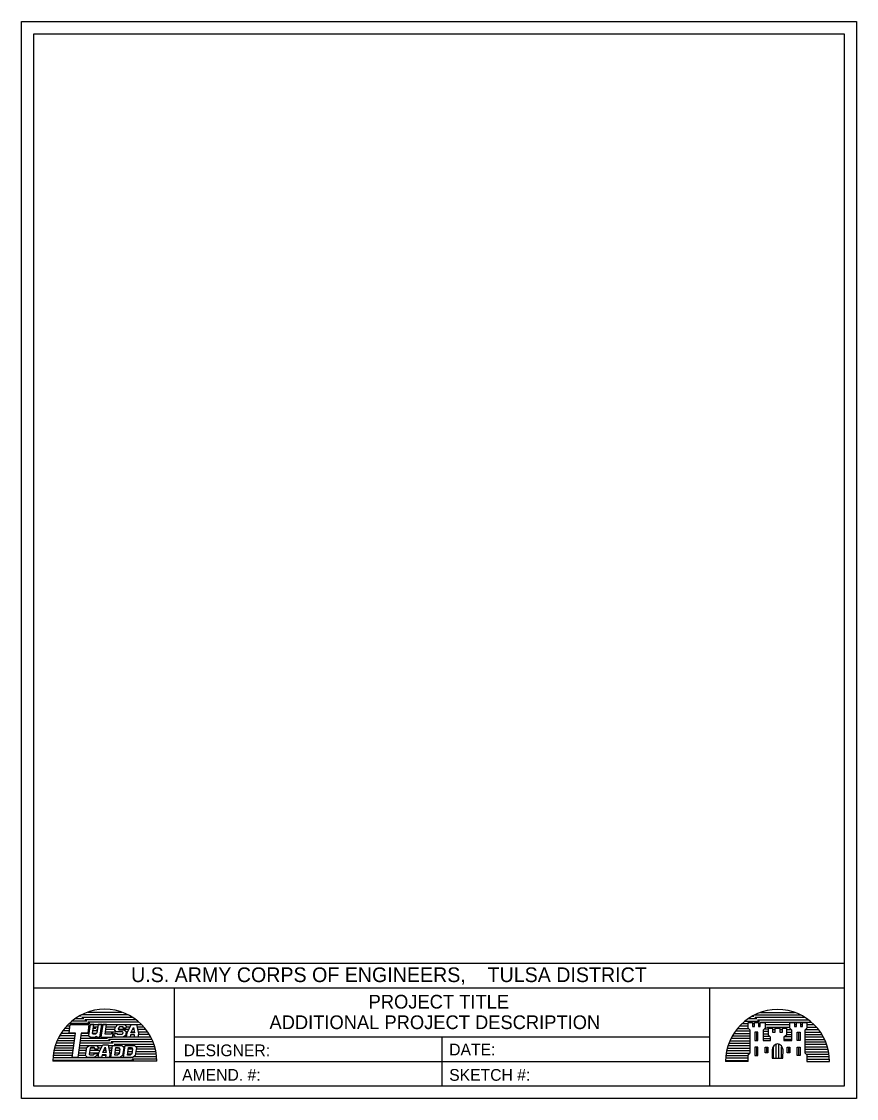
# Model space of a CAD drawing. Extents: x -12225.15 to -12224.44, y -12111.632 to -12110.717.
import ezdxf

# ---------------------------------------------------------------- set-up
doc = ezdxf.new("R2010")
doc.units = 0
for name, color, linetype in [('G-ANNO-SYMB', 7, 'Continuous'), ('G-ANNO-TEXT', 7, 'Continuous'), ('G-ANNO-TTLB', 7, 'Continuous')]:
    doc.layers.add(name, color=color, linetype=linetype)

msp = doc.modelspace()

# ---------------------------------------------------------------- linework, layer by layer
at = {"layer": 'G-ANNO-SYMB'}
for p, q in [((-12225.09726, -12111.56405), (-12225.10484, -12111.56405)), ((-12225.09975, -12111.56196), (-12225.10156, -12111.56196)), ((-12225.09896, -12111.56056), (-12225.06005, -12111.56056)), ((-12225.09893, -12111.56267), (-12225.05626, -12111.56267)), ((-12225.09394, -12111.55848), (-12225.06506, -12111.55848)), ((-12224.52524, -12111.56426), (-12224.53283, -12111.56426)), ((-12224.52773, -12111.56218), (-12224.52954, -12111.56218)), ((-12224.52694, -12111.56078), (-12224.48803, -12111.56078)), ((-12224.52691, -12111.56288), (-12224.48425, -12111.56288)), ((-12224.52191, -12111.5587), (-12224.49304, -12111.5587)), ((-12225.10934, -12111.57241), (-12225.11381, -12111.57241)), ((-12225.10907, -12111.5703), (-12225.11201, -12111.5703)), ((-12225.09228, -12111.56823), (-12225.10996, -12111.56823)), ((-12225.09477, -12111.56614), (-12225.10759, -12111.56614)), ((-12225.09644, -12111.56474), (-12225.0532, -12111.56474)), ((-12225.09394, -12111.56683), (-12225.05059, -12111.56683)), ((-12225.09246, -12111.57241), (-12225.0935, -12111.57241)), ((-12225.09211, -12111.5703), (-12225.09324, -12111.5703)), ((-12225.09145, -12111.56892), (-12225.04833, -12111.56892)), ((-12225.0873, -12111.57241), (-12225.08945, -12111.57241)), ((-12225.08896, -12111.57102), (-12225.0854, -12111.57102)), ((-12225.08648, -12111.57309), (-12225.08571, -12111.57309)), ((-12225.08267, -12111.57309), (-12225.08178, -12111.57309)), ((-12225.08242, -12111.57102), (-12225.08146, -12111.57102)), ((-12225.07869, -12111.57309), (-12225.07086, -12111.57309)), ((-12225.07836, -12111.57102), (-12225.07023, -12111.57102)), ((-12225.06815, -12111.57309), (-12225.05899, -12111.57309)), ((-12225.06133, -12111.57102), (-12225.05804, -12111.57102)), ((-12225.05596, -12111.57309), (-12225.05475, -12111.57309)), ((-12225.05199, -12111.57102), (-12225.04636, -12111.57102)), ((-12225.05161, -12111.57309), (-12225.04464, -12111.57309)), ((-12224.53218, -12111.57261), (-12224.54179, -12111.57261)), ((-12224.5326, -12111.57053), (-12224.53999, -12111.57053)), ((-12224.5326, -12111.56845), (-12224.53794, -12111.56845)), ((-12224.52275, -12111.56635), (-12224.53558, -12111.56635)), ((-12224.52717, -12111.56845), (-12224.52889, -12111.56845)), ((-12224.52442, -12111.56497), (-12224.48117, -12111.56497)), ((-12224.5222, -12111.56845), (-12224.52378, -12111.56845)), ((-12224.52192, -12111.56705), (-12224.47856, -12111.56705)), ((-12224.51843, -12111.57261), (-12224.51528, -12111.57261)), ((-12224.518, -12111.56914), (-12224.49711, -12111.56914)), ((-12224.51694, -12111.57123), (-12224.49706, -12111.57123)), ((-12224.51178, -12111.57331), (-12224.50963, -12111.57331)), ((-12224.50545, -12111.57331), (-12224.50343, -12111.57331)), ((-12224.50001, -12111.57331), (-12224.49606, -12111.57331)), ((-12224.49293, -12111.56914), (-12224.49132, -12111.56914)), ((-12224.48788, -12111.56914), (-12224.48634, -12111.56914)), ((-12224.4835, -12111.57331), (-12224.47261, -12111.57331)), ((-12224.48254, -12111.57123), (-12224.47434, -12111.57123)), ((-12224.48249, -12111.56914), (-12224.4763, -12111.56914)), ((-12225.105, -12111.58076), (-12225.11917, -12111.58076)), ((-12225.10457, -12111.57866), (-12225.11807, -12111.57866)), ((-12225.10435, -12111.57658), (-12225.11682, -12111.57658)), ((-12225.10959, -12111.57449), (-12225.11542, -12111.57449)), ((-12225.07734, -12111.58076), (-12225.10013, -12111.58076)), ((-12225.09289, -12111.57866), (-12225.09983, -12111.57866)), ((-12225.09303, -12111.57658), (-12225.09954, -12111.57658)), ((-12225.09273, -12111.57449), (-12225.09376, -12111.57449)), ((-12225.08682, -12111.57658), (-12225.09007, -12111.57658)), ((-12225.08593, -12111.57449), (-12225.08976, -12111.57449)), ((-12225.0826, -12111.57866), (-12225.08357, -12111.57866)), ((-12225.08232, -12111.57658), (-12225.08327, -12111.57658)), ((-12225.08306, -12111.57519), (-12225.08209, -12111.57519)), ((-12225.07902, -12111.57519), (-12225.07008, -12111.57519)), ((-12225.07652, -12111.58145), (-12225.03951, -12111.58145)), ((-12225.07292, -12111.57938), (-12225.07058, -12111.57938)), ((-12225.07258, -12111.57727), (-12225.0715, -12111.57727)), ((-12225.06329, -12111.57938), (-12225.06101, -12111.57938)), ((-12225.06181, -12111.57727), (-12225.06072, -12111.57727)), ((-12225.06133, -12111.57519), (-12225.06011, -12111.57519)), ((-12225.05792, -12111.57938), (-12225.05439, -12111.57938)), ((-12225.05692, -12111.57519), (-12225.05439, -12111.57519)), ((-12225.05125, -12111.57519), (-12225.04309, -12111.57519)), ((-12225.05122, -12111.57938), (-12225.04056, -12111.57938)), ((-12225.051, -12111.57727), (-12225.04176, -12111.57727)), ((-12224.53089, -12111.58097), (-12224.54714, -12111.58097)), ((-12224.53089, -12111.57889), (-12224.54605, -12111.57889)), ((-12224.53089, -12111.5768), (-12224.54479, -12111.5768)), ((-12224.53089, -12111.57471), (-12224.54339, -12111.57471)), ((-12224.52548, -12111.57557), (-12224.52548, -12111.58268)), ((-12224.51971, -12111.57471), (-12224.51508, -12111.57471)), ((-12224.51971, -12111.5768), (-12224.51508, -12111.5768)), ((-12224.51971, -12111.57889), (-12224.51425, -12111.57889)), ((-12224.51971, -12111.58097), (-12224.51339, -12111.58097)), ((-12224.51178, -12111.57541), (-12224.50963, -12111.57541)), ((-12224.50545, -12111.57541), (-12224.50343, -12111.57541)), ((-12224.4955, -12111.58167), (-12224.50218, -12111.58167)), ((-12224.4955, -12111.57958), (-12224.50194, -12111.57958)), ((-12224.50002, -12111.57541), (-12224.4955, -12111.57541)), ((-12224.50002, -12111.57749), (-12224.4955, -12111.57749)), ((-12224.48964, -12111.57557), (-12224.48964, -12111.58268)), ((-12224.4842, -12111.57541), (-12224.47108, -12111.57541)), ((-12224.4842, -12111.57749), (-12224.46973, -12111.57749)), ((-12224.4842, -12111.57958), (-12224.46853, -12111.57958)), ((-12224.4842, -12111.58167), (-12224.46748, -12111.58167)), ((-12225.1065, -12111.5912), (-12225.12277, -12111.5912)), ((-12225.10619, -12111.58911), (-12225.12226, -12111.58911)), ((-12225.10586, -12111.58701), (-12225.12167, -12111.58701)), ((-12225.10556, -12111.58494), (-12225.12095, -12111.58494)), ((-12225.10527, -12111.58284), (-12225.12011, -12111.58284)), ((-12225.09523, -12111.5912), (-12225.10159, -12111.5912)), ((-12225.09492, -12111.58911), (-12225.10134, -12111.58911)), ((-12225.093, -12111.58701), (-12225.101, -12111.58701)), ((-12225.07238, -12111.58494), (-12225.10073, -12111.58494)), ((-12225.07486, -12111.58284), (-12225.10043, -12111.58284)), ((-12225.08377, -12111.5912), (-12225.09225, -12111.5912)), ((-12225.08823, -12111.58911), (-12225.09193, -12111.58911)), ((-12225.08167, -12111.58701), (-12225.08649, -12111.58701)), ((-12225.08273, -12111.58911), (-12225.08521, -12111.58911)), ((-12225.07854, -12111.5912), (-12225.08063, -12111.5912)), ((-12225.07895, -12111.58911), (-12225.0796, -12111.58911)), ((-12225.07303, -12111.58701), (-12225.07649, -12111.58701)), ((-12225.07333, -12111.58911), (-12225.07607, -12111.58911)), ((-12225.07366, -12111.5912), (-12225.07567, -12111.5912)), ((-12225.07403, -12111.58354), (-12225.03859, -12111.58354)), ((-12225.07155, -12111.58563), (-12225.0378, -12111.58563)), ((-12225.06696, -12111.5912), (-12225.07053, -12111.5912)), ((-12225.06741, -12111.58911), (-12225.07021, -12111.58911)), ((-12225.0642, -12111.58772), (-12225.06228, -12111.58772)), ((-12225.06399, -12111.5919), (-12225.06295, -12111.5919)), ((-12225.06369, -12111.5898), (-12225.06259, -12111.5898)), ((-12225.05974, -12111.5919), (-12225.05623, -12111.5919)), ((-12225.05947, -12111.5898), (-12225.05593, -12111.5898)), ((-12225.05334, -12111.58772), (-12225.03713, -12111.58772)), ((-12225.05314, -12111.5919), (-12225.03613, -12111.5919)), ((-12225.05285, -12111.5898), (-12225.03656, -12111.5898)), ((-12224.53089, -12111.59141), (-12224.55073, -12111.59141)), ((-12224.53089, -12111.58932), (-12224.55025, -12111.58932)), ((-12224.53089, -12111.58724), (-12224.54964, -12111.58724)), ((-12224.53089, -12111.58516), (-12224.54894, -12111.58516)), ((-12224.53089, -12111.58305), (-12224.5481, -12111.58305)), ((-12224.52548, -12111.58829), (-12224.52548, -12111.59541)), ((-12224.51694, -12111.58813), (-12224.51694, -12111.5931)), ((-12224.51085, -12111.59764), (-12224.51085, -12111.58793)), ((-12224.50861, -12111.59764), (-12224.50861, -12111.58602)), ((-12224.5064, -12111.59764), (-12224.5064, -12111.58601)), ((-12224.50417, -12111.59764), (-12224.50417, -12111.58793)), ((-12224.49817, -12111.58813), (-12224.49817, -12111.5931)), ((-12224.48964, -12111.58829), (-12224.48964, -12111.59541)), ((-12224.4842, -12111.58376), (-12224.46657, -12111.58376)), ((-12224.4842, -12111.58584), (-12224.46578, -12111.58584)), ((-12224.4842, -12111.58794), (-12224.46511, -12111.58794)), ((-12224.4842, -12111.59002), (-12224.46455, -12111.59002)), ((-12225.05496, -12111.59955), (-12225.12371, -12111.59955)), ((-12225.03532, -12111.60025), (-12225.12371, -12111.60025)), ((-12225.05745, -12111.59746), (-12225.1236, -12111.59746)), ((-12225.10706, -12111.59536), (-12225.12342, -12111.59536)), ((-12225.10678, -12111.59329), (-12225.12315, -12111.59329)), ((-12225.09569, -12111.59536), (-12225.10232, -12111.59536)), ((-12225.09555, -12111.59329), (-12225.10195, -12111.59329)), ((-12225.08483, -12111.59329), (-12225.09257, -12111.59329)), ((-12225.08497, -12111.59536), (-12225.08635, -12111.59536)), ((-12225.07827, -12111.59536), (-12225.082, -12111.59536)), ((-12225.0741, -12111.59536), (-12225.07531, -12111.59536)), ((-12225.07397, -12111.59329), (-12225.07525, -12111.59329)), ((-12225.06722, -12111.59329), (-12225.07086, -12111.59329)), ((-12225.06343, -12111.59536), (-12225.06445, -12111.59536)), ((-12225.06011, -12111.59398), (-12225.05652, -12111.59398)), ((-12225.05661, -12111.59815), (-12225.03536, -12111.59815)), ((-12225.05464, -12111.59607), (-12225.03551, -12111.59607)), ((-12225.05344, -12111.59398), (-12225.03575, -12111.59398)), ((-12224.5326, -12111.59976), (-12224.55168, -12111.59976)), ((-12224.5326, -12111.60046), (-12224.55168, -12111.60046)), ((-12224.5326, -12111.59768), (-12224.55158, -12111.59768)), ((-12224.5326, -12111.59559), (-12224.5514, -12111.59559)), ((-12224.53123, -12111.59351), (-12224.55113, -12111.59351)), ((-12224.4842, -12111.5921), (-12224.46409, -12111.5921)), ((-12224.48311, -12111.5942), (-12224.46374, -12111.5942)), ((-12224.48251, -12111.59629), (-12224.46349, -12111.59629)), ((-12224.48251, -12111.59838), (-12224.46334, -12111.59838)), ((-12224.48251, -12111.60046), (-12224.46329, -12111.60046))]:
    msp.add_line(p, q, dxfattribs=at)
for points in [[(-12225.10894, -12111.5691), (-12225.09309, -12111.5691), (-12225.09399, -12111.57632), (-12225.0995, -12111.57632), (-12225.10245, -12111.59695), (-12225.10725, -12111.59695), (-12225.10431, -12111.57632), (-12225.10982, -12111.57632), (-12225.10894, -12111.5691)], [(-12225.09195, -12111.5691), (-12225.09328, -12111.57827), (-12225.09168, -12111.57989), (-12225.08794, -12111.57989), (-12225.08652, -12111.57881), (-12225.0867, -12111.57989), (-12225.08375, -12111.57989), (-12225.08215, -12111.5691), (-12225.08509, -12111.5691), (-12225.08617, -12111.57606), (-12225.0875, -12111.57711), (-12225.08955, -12111.57711), (-12225.09007, -12111.57659), (-12225.08893, -12111.5691), (-12225.09195, -12111.5691)], [(-12225.0812, -12111.5691), (-12225.08278, -12111.57989), (-12225.08278, -12111.57989), (-12225.07299, -12111.57989), (-12225.07247, -12111.57659), (-12225.07407, -12111.57659), (-12225.07415, -12111.57711), (-12225.07932, -12111.57711), (-12225.07807, -12111.5691), (-12225.0812, -12111.5691)], [(-12225.07139, -12111.57659), (-12225.06891, -12111.57659), (-12225.06899, -12111.57711), (-12225.0648, -12111.57711), (-12225.0641, -12111.57659), (-12225.06402, -12111.57589), (-12225.06454, -12111.57534), (-12225.06998, -12111.57534), (-12225.07096, -12111.57382), (-12225.07059, -12111.57144), (-12225.06848, -12111.5691), (-12225.06269, -12111.5691), (-12225.06135, -12111.57046), (-12225.06161, -12111.57216), (-12225.06402, -12111.57216), (-12225.06383, -12111.57107), (-12225.06703, -12111.57107), (-12225.06802, -12111.57216), (-12225.06821, -12111.57302), (-12225.06766, -12111.57347), (-12225.06303, -12111.57347), (-12225.06145, -12111.57507), (-12225.06197, -12111.57827), (-12225.06392, -12111.57989), (-12225.07008, -12111.57989), (-12225.07167, -12111.57827), (-12225.07139, -12111.57659)], [(-12225.06108, -12111.57989), (-12225.06055, -12111.57606), (-12225.05707, -12111.5691), (-12225.05245, -12111.5691), (-12225.05094, -12111.57676), (-12225.0514, -12111.57989), (-12225.05442, -12111.57989), (-12225.05415, -12111.57783), (-12225.05771, -12111.57783), (-12225.05805, -12111.57989), (-12225.06108, -12111.57989)], [(-12225.05729, -12111.57596), (-12225.05508, -12111.57142), (-12225.0542, -12111.57596), (-12225.05729, -12111.57596)], [(-12224.5326, -12111.60046), (-12224.5326, -12111.59515), (-12224.53089, -12111.5931), (-12224.53089, -12111.57391), (-12224.5326, -12111.57221), (-12224.5326, -12111.56722), (-12224.52885, -12111.56722), (-12224.52885, -12111.57059), (-12224.52717, -12111.57059), (-12224.52717, -12111.56722), (-12224.52378, -12111.56722), (-12224.52378, -12111.57059), (-12224.5222, -12111.57059), (-12224.5222, -12111.56722), (-12224.518, -12111.56722), (-12224.518, -12111.57221), (-12224.51971, -12111.57391), (-12224.51971, -12111.58268), (-12224.51339, -12111.58268), (-12224.51339, -12111.57977), (-12224.51508, -12111.57807), (-12224.51508, -12111.57221), (-12224.51178, -12111.57221), (-12224.51178, -12111.57557), (-12224.50963, -12111.57557), (-12224.50963, -12111.57221), (-12224.50547, -12111.57221), (-12224.50547, -12111.57557), (-12224.50342, -12111.57557), (-12224.50342, -12111.57221), (-12224.50002, -12111.57221), (-12224.50002, -12111.57807), (-12224.50218, -12111.57977), (-12224.50218, -12111.58268), (-12224.4955, -12111.58268), (-12224.4955, -12111.57391), (-12224.49711, -12111.57221), (-12224.49711, -12111.56722), (-12224.49301, -12111.56722), (-12224.49301, -12111.57059), (-12224.49132, -12111.57059), (-12224.49132, -12111.56722), (-12224.48795, -12111.56722), (-12224.48795, -12111.57059), (-12224.48634, -12111.57059), (-12224.48634, -12111.56722), (-12224.48251, -12111.56722), (-12224.48251, -12111.57221), (-12224.4842, -12111.57391), (-12224.4842, -12111.5931), (-12224.48251, -12111.59479), (-12224.48251, -12111.60046)], [(-12225.09274, -12111.5868), (-12225.0867, -12111.5868), (-12225.08509, -12111.58843), (-12225.08535, -12111.59001), (-12225.08804, -12111.59001), (-12225.08794, -12111.58931), (-12225.08849, -12111.58868), (-12225.09122, -12111.58868), (-12225.09195, -12111.58923), (-12225.09274, -12111.5943), (-12225.09222, -12111.59481), (-12225.08936, -12111.59481), (-12225.08865, -12111.5943), (-12225.08856, -12111.59376), (-12225.08599, -12111.59376), (-12225.08617, -12111.59535), (-12225.08822, -12111.59695), (-12225.09426, -12111.59695), (-12225.09586, -12111.59526), (-12225.09481, -12111.58843), (-12225.09274, -12111.5868)], [(-12225.08526, -12111.59695), (-12225.08474, -12111.5931), (-12225.08125, -12111.58619), (-12225.07666, -12111.58619), (-12225.07514, -12111.59384), (-12225.07558, -12111.59695), (-12225.0786, -12111.59695), (-12225.07834, -12111.59491), (-12225.0819, -12111.59491), (-12225.08225, -12111.59695), (-12225.08526, -12111.59695)], [(-12225.08135, -12111.59269), (-12225.07915, -12111.58815), (-12225.07825, -12111.59269), (-12225.08135, -12111.59269)], [(-12225.07452, -12111.59695), (-12225.07299, -12111.5868), (-12225.06508, -12111.5868), (-12225.06348, -12111.58843), (-12225.06447, -12111.59526), (-12225.06658, -12111.59695), (-12225.07452, -12111.59695)], [(-12225.07113, -12111.59501), (-12225.07014, -12111.58868), (-12225.06776, -12111.58868), (-12225.06678, -12111.58985), (-12225.0673, -12111.59393), (-12225.06874, -12111.59501), (-12225.07113, -12111.59501)], [(-12225.06367, -12111.59695), (-12225.06215, -12111.5868), (-12225.05424, -12111.5868), (-12225.05265, -12111.58843), (-12225.05361, -12111.59526), (-12225.05575, -12111.59695), (-12225.06367, -12111.59695)], [(-12225.06027, -12111.59501), (-12225.0593, -12111.58868), (-12225.05691, -12111.58868), (-12225.05592, -12111.58985), (-12225.05647, -12111.59393), (-12225.05788, -12111.59501), (-12225.06027, -12111.59501)], [(-12224.51214, -12111.5906), (-12224.51214, -12111.59764), (-12224.50288, -12111.59764), (-12224.50285, -12111.5906)]]:
    msp.add_lwpolyline(points, dxfattribs=at)
for points in [[(-12224.52424, -12111.57557), (-12224.52673, -12111.57557), (-12224.52673, -12111.58268), (-12224.52424, -12111.58268)], [(-12224.49088, -12111.57557), (-12224.4884, -12111.57557), (-12224.4884, -12111.58268), (-12224.49088, -12111.58268)], [(-12224.52424, -12111.58829), (-12224.52673, -12111.58829), (-12224.52673, -12111.59541), (-12224.52424, -12111.59541)], [(-12224.518, -12111.58813), (-12224.51588, -12111.58813), (-12224.51588, -12111.5931), (-12224.518, -12111.5931)], [(-12224.49924, -12111.58813), (-12224.49711, -12111.58813), (-12224.49711, -12111.5931), (-12224.49924, -12111.5931)], [(-12224.49088, -12111.58829), (-12224.4884, -12111.58829), (-12224.4884, -12111.59541), (-12224.49088, -12111.59541)]]:
    msp.add_lwpolyline(points, close=True, dxfattribs=at)
for centre, radius, start, end in [((-12225.0795, -12111.60024), 0.04419, 0, 180), ((-12224.50748, -12111.60046), 0.04419, 0, 180), ((-12224.50679, -12111.59087), 0.00539, 97.72175, 177.14315), ((-12224.50823, -12111.59087), 0.00539, 2.85685, 82.27825)]:
    msp.add_arc(centre, radius, start, end, dxfattribs=at)
at = {"layer": 'G-ANNO-TEXT'}
msp.add_line((-12224.79264, -12111.62144), (-12224.79264, -12111.57977), dxfattribs=at)
at = {"layer": 'G-ANNO-TTLB'}
for p, q in [((-12225.15034, -12111.63185), (-12225.15034, -12110.71666)), ((-12225.15034, -12110.71666), (-12224.4404, -12110.71666)), ((-12224.4404, -12110.71666), (-12224.4404, -12111.63185)), ((-12225.13993, -12111.62144), (-12225.13993, -12110.72707)), ((-12225.13993, -12110.72707), (-12224.45081, -12110.72707)), ((-12224.45081, -12110.72707), (-12224.45081, -12111.62144)), ((-12224.45081, -12111.51727), (-12225.13993, -12111.51727)), ((-12224.45081, -12111.5381), (-12225.13993, -12111.5381)), ((-12225.0202, -12111.62144), (-12225.0202, -12111.5381)), ((-12224.56508, -12111.62144), (-12224.56508, -12111.5381)), ((-12224.56508, -12111.57977), (-12225.0202, -12111.57977)), ((-12224.56508, -12111.6006), (-12225.0202, -12111.6006)), ((-12224.45081, -12111.62144), (-12225.13993, -12111.62144)), ((-12224.4404, -12111.63185), (-12225.15034, -12111.63185))]:
    msp.add_line(p, q, dxfattribs=at)

# ---------------------------------------------------------------- texts
at = {"layer": 'G-ANNO-TEXT'}
for s, height, p in [('U.S. ARMY CORPS OF ENGINEERS,    TULSA DISTRICT', 0.0124766, (-12225.0572, -12111.53296)), ('PROJECT TITLE', 0.0116458, (-12224.85522, -12111.55544)), ('ADDITIONAL PROJECT DESCRIPTION', 0.0116458, (-12224.93953, -12111.57291)), ('DESIGNER:', 0.009979, (-12225.01239, -12111.59595)), ('DATE:', 0.009979, (-12224.7867, -12111.59525)), ('AMEND. #:', 0.009979, (-12225.01377, -12111.61676)), ('SKETCH #:', 0.009979, (-12224.7867, -12111.61683))]:
    msp.add_text(s, height=height, dxfattribs=at).set_placement(p)

doc.saveas('drawing.dxf')
